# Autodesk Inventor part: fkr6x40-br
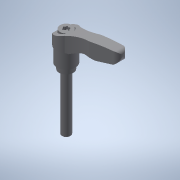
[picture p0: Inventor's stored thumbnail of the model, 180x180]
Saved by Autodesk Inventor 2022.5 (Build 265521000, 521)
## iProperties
Created: 2017-09
Part Number: fkr6x40-br
Material: 一般
Document SubType Name: Modeling
Designer: imaocorp
Density: 1 g/cm^3
Appearance: 既定
Author: imaocorp
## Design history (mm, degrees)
node "fkr6x40-br.x_t1"
node "fkr6x40-br"
node "Base1"
